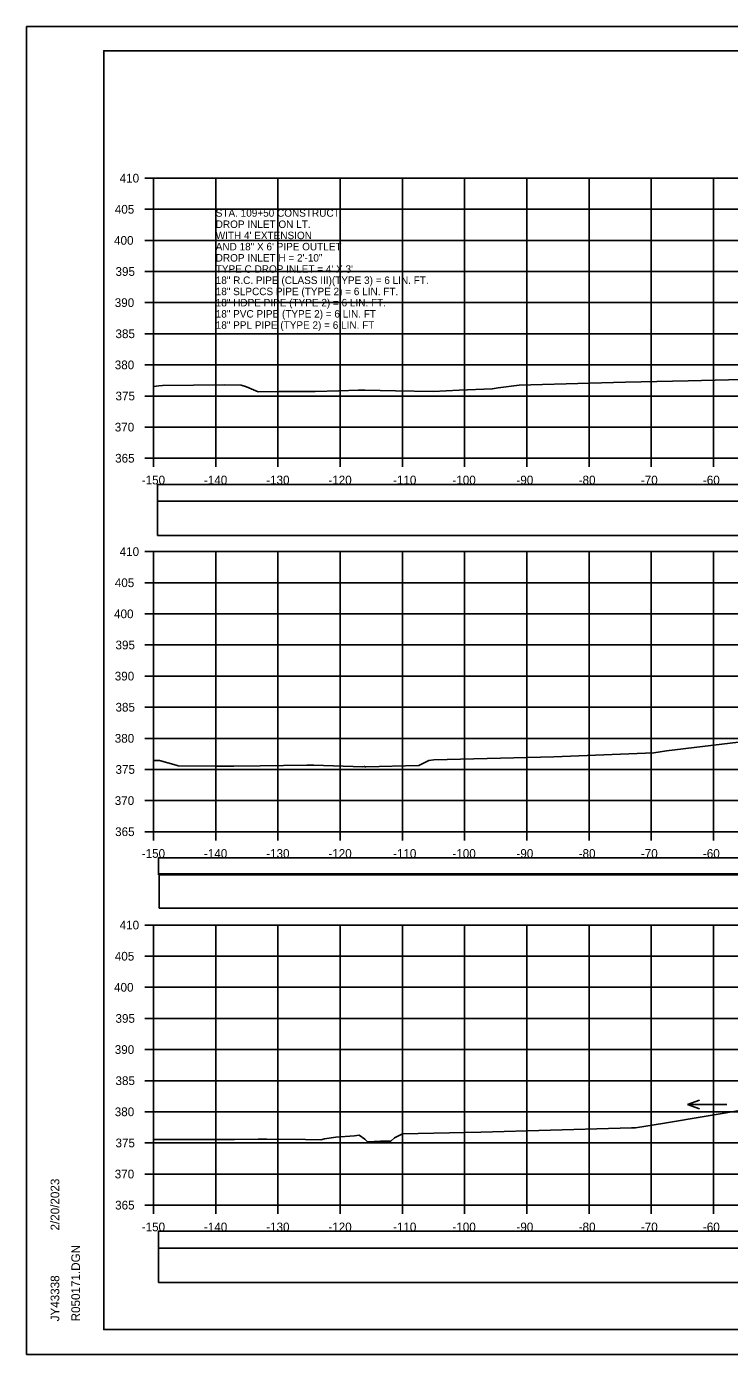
# Model space of a CAD drawing. Extents: x -37291014 to -37290680, y -936053 to -933067.
# Drawn here: x -37291013.5 to -37290900.5, y -934346.6 to -934133.3 of the extents above; entities that cross this region are included whole.
import ezdxf

# ---------------------------------------------------------------- set-up
doc = ezdxf.new("R2010")
doc.units = 0
for name, color, linetype in [('Default', 7, 'Continuous'), ('R_Axis', 7, 'Continuous'), ('R_Axis Annot', 7, 'Continuous'), ('R_Border', 7, 'Continuous'), ('R_Exist Surface', 7, 'Continuous'), ('R_Grid', 7, 'Continuous'), ('R_No Plot', 7, 'Continuous'), ('R_Water Annot', 7, 'Continuous')]:
    doc.layers.add(name, color=color, linetype=linetype)

msp = doc.modelspace()

# ---------------------------------------------------------------- linework, layer by layer
at = {"layer": 'Default'}
for points in [[(-37290992.48, -934209.53), (-37290693.72, -934209.53), (-37290693.72, -934206.82), (-37290992.48, -934206.82)], [(-37290992.48, -934215.05), (-37290693.72, -934215.05), (-37290693.72, -934209.53), (-37290992.48, -934209.53)], [(-37290992.31, -934269.53), (-37290693.89, -934269.53), (-37290693.89, -934266.82), (-37290992.31, -934266.82)], [(-37290992.18, -934274.93), (-37290693.77, -934274.93), (-37290693.77, -934269.4), (-37290992.18, -934269.4)], [(-37290992.31, -934329.53), (-37290693.89, -934329.53), (-37290693.89, -934326.82), (-37290992.31, -934326.82)], [(-37290992.31, -934335.05), (-37290693.89, -934335.05), (-37290693.89, -934329.53), (-37290992.31, -934329.53)]]:
    msp.add_lwpolyline(points, close=True, dxfattribs=at)
at = {"layer": 'R_Axis'}
for p, q in [((-37290994.5, -934157.62), (-37290993.1, -934157.62)), ((-37290993.1, -934202.62), (-37290993.1, -934157.62)), ((-37290994.5, -934162.62), (-37290993.1, -934162.62)), ((-37290994.5, -934167.62), (-37290993.1, -934167.62)), ((-37290994.5, -934172.62), (-37290993.1, -934172.62)), ((-37290994.5, -934177.62), (-37290993.1, -934177.62)), ((-37290994.5, -934182.62), (-37290993.1, -934182.62)), ((-37290994.5, -934187.62), (-37290993.1, -934187.62)), ((-37290994.5, -934192.62), (-37290993.1, -934192.62)), ((-37290994.5, -934197.62), (-37290993.1, -934197.62)), ((-37290994.5, -934202.62), (-37290993.1, -934202.62)), ((-37290993.1, -934202.62), (-37290693.1, -934202.62)), ((-37290993.1, -934204.02), (-37290993.1, -934202.62)), ((-37290983.1, -934204.02), (-37290983.1, -934202.62)), ((-37290973.1, -934204.02), (-37290973.1, -934202.62)), ((-37290963.1, -934204.02), (-37290963.1, -934202.62)), ((-37290953.1, -934204.02), (-37290953.1, -934202.62)), ((-37290943.1, -934204.02), (-37290943.1, -934202.62)), ((-37290933.1, -934204.02), (-37290933.1, -934202.62)), ((-37290923.1, -934204.02), (-37290923.1, -934202.62)), ((-37290913.1, -934204.02), (-37290913.1, -934202.62)), ((-37290903.1, -934204.02), (-37290903.1, -934202.62)), ((-37290994.5, -934217.62), (-37290993.1, -934217.62)), ((-37290993.1, -934262.62), (-37290993.1, -934217.62)), ((-37290994.5, -934222.62), (-37290993.1, -934222.62)), ((-37290994.5, -934227.62), (-37290993.1, -934227.62)), ((-37290994.5, -934232.62), (-37290993.1, -934232.62)), ((-37290994.5, -934237.62), (-37290993.1, -934237.62)), ((-37290994.5, -934242.62), (-37290993.1, -934242.62)), ((-37290994.5, -934247.62), (-37290993.1, -934247.62)), ((-37290994.5, -934252.62), (-37290993.1, -934252.62)), ((-37290994.5, -934257.62), (-37290993.1, -934257.62)), ((-37290994.5, -934262.62), (-37290993.1, -934262.62)), ((-37290993.1, -934262.62), (-37290693.1, -934262.62)), ((-37290993.1, -934264.02), (-37290993.1, -934262.62)), ((-37290983.1, -934264.02), (-37290983.1, -934262.62)), ((-37290973.1, -934264.02), (-37290973.1, -934262.62)), ((-37290963.1, -934264.02), (-37290963.1, -934262.62)), ((-37290953.1, -934264.02), (-37290953.1, -934262.62)), ((-37290943.1, -934264.02), (-37290943.1, -934262.62)), ((-37290933.1, -934264.02), (-37290933.1, -934262.62)), ((-37290923.1, -934264.02), (-37290923.1, -934262.62)), ((-37290913.1, -934264.02), (-37290913.1, -934262.62)), ((-37290903.1, -934264.02), (-37290903.1, -934262.62)), ((-37290994.5, -934277.62), (-37290993.1, -934277.62)), ((-37290993.1, -934322.62), (-37290993.1, -934277.62)), ((-37290994.5, -934282.62), (-37290993.1, -934282.62)), ((-37290994.5, -934287.62), (-37290993.1, -934287.62)), ((-37290994.5, -934292.62), (-37290993.1, -934292.62)), ((-37290994.5, -934297.62), (-37290993.1, -934297.62)), ((-37290994.5, -934302.62), (-37290993.1, -934302.62)), ((-37290994.5, -934307.62), (-37290993.1, -934307.62)), ((-37290994.5, -934312.62), (-37290993.1, -934312.62)), ((-37290994.5, -934317.62), (-37290993.1, -934317.62)), ((-37290994.5, -934322.62), (-37290993.1, -934322.62)), ((-37290993.1, -934322.62), (-37290693.1, -934322.62)), ((-37290993.1, -934324.02), (-37290993.1, -934322.62)), ((-37290983.1, -934324.02), (-37290983.1, -934322.62)), ((-37290973.1, -934324.02), (-37290973.1, -934322.62)), ((-37290963.1, -934324.02), (-37290963.1, -934322.62)), ((-37290953.1, -934324.02), (-37290953.1, -934322.62)), ((-37290943.1, -934324.02), (-37290943.1, -934322.62)), ((-37290933.1, -934324.02), (-37290933.1, -934322.62)), ((-37290923.1, -934324.02), (-37290923.1, -934322.62)), ((-37290913.1, -934324.02), (-37290913.1, -934322.62)), ((-37290903.1, -934324.02), (-37290903.1, -934322.62))]:
    msp.add_line(p, q, dxfattribs=at)
at = {"layer": 'R_Border'}
for p, q in [((-37291001.1, -934137.16), (-37290684.92, -934137.16)), ((-37291001.1, -934342.62), (-37291001.1, -934137.16)), ((-37291001.1, -934342.62), (-37291001.1, -934342.62)), ((-37290684.92, -934342.62), (-37291001.1, -934342.62))]:
    msp.add_line(p, q, dxfattribs=at)
at = {"layer": 'R_Exist Surface'}
for points in [[(-37290993.1, -934191.09), (-37290992.27, -934191), (-37290991.67, -934190.92), (-37290981.71, -934190.85), (-37290979.01, -934190.86), (-37290978.15, -934191.16), (-37290976.28, -934191.95), (-37290972.92, -934191.91), (-37290969.06, -934191.92), (-37290967.13, -934191.88), (-37290963.33, -934191.78), (-37290960.15, -934191.7), (-37290959.16, -934191.67), (-37290954.21, -934191.77), (-37290948.14, -934191.9), (-37290943.97, -934191.69), (-37290938.64, -934191.49), (-37290937.71, -934191.31), (-37290934.34, -934190.87), (-37290923, -934190.55), (-37290917.26, -934190.42), (-37290907.16, -934190.16), (-37290896.32, -934189.93)], [(-37290993.1, -934251.16), (-37290992.14, -934251.16), (-37290989.45, -934251.91), (-37290989.13, -934252.03), (-37290983.05, -934252.07), (-37290980.18, -934252.07), (-37290975.95, -934252.04), (-37290968.48, -934251.95), (-37290967.33, -934251.95), (-37290959.45, -934252.18), (-37290959.2, -934252.12), (-37290959.08, -934252.2), (-37290958.98, -934252.18), (-37290950.48, -934251.98), (-37290948.86, -934251.19), (-37290948.04, -934251.07), (-37290928.77, -934250.58), (-37290912.66, -934249.96), (-37290910.65, -934249.64), (-37290891.49, -934247.31)], [(-37290993.1, -934312.05), (-37290991.48, -934312.06), (-37290986.25, -934312.09), (-37290980.1, -934312.06), (-37290976.26, -934312.03), (-37290974.89, -934312.02), (-37290968.69, -934312.06), (-37290966.2, -934312.13), (-37290965.62, -934311.97), (-37290963.78, -934311.68), (-37290960.82, -934311.49), (-37290960.02, -934311.38), (-37290959.11, -934312.02), (-37290958.71, -934312.46), (-37290956.62, -934312.33), (-37290954.93, -934312.33), (-37290954.35, -934311.78), (-37290953.07, -934311.18), (-37290940.48, -934310.9), (-37290918.09, -934310.25), (-37290916.26, -934310.2), (-37290915.63, -934310.18), (-37290910.94, -934309.42), (-37290877.81, -934303.86)]]:
    msp.add_lwpolyline(points, dxfattribs=at)
at = {"layer": 'R_Grid'}
for p, q in [((-37290993.1, -934157.62), (-37290693.1, -934157.62)), ((-37290993.1, -934202.62), (-37290993.1, -934157.62)), ((-37290983.1, -934202.62), (-37290983.1, -934157.62)), ((-37290973.1, -934202.62), (-37290973.1, -934157.62)), ((-37290963.1, -934202.62), (-37290963.1, -934157.62)), ((-37290953.1, -934202.62), (-37290953.1, -934157.62)), ((-37290943.1, -934202.62), (-37290943.1, -934157.62)), ((-37290933.1, -934202.62), (-37290933.1, -934157.62)), ((-37290923.1, -934202.62), (-37290923.1, -934157.62)), ((-37290913.1, -934202.62), (-37290913.1, -934157.62)), ((-37290903.1, -934202.62), (-37290903.1, -934157.62)), ((-37290993.1, -934162.62), (-37290693.1, -934162.62)), ((-37290993.1, -934167.62), (-37290693.1, -934167.62)), ((-37290993.1, -934172.62), (-37290693.1, -934172.62)), ((-37290993.1, -934177.62), (-37290693.1, -934177.62)), ((-37290993.1, -934182.62), (-37290693.1, -934182.62)), ((-37290993.1, -934187.62), (-37290693.1, -934187.62)), ((-37290993.1, -934192.62), (-37290693.1, -934192.62)), ((-37290993.1, -934197.62), (-37290693.1, -934197.62)), ((-37290993.1, -934202.62), (-37290693.1, -934202.62)), ((-37290993.1, -934217.62), (-37290693.1, -934217.62)), ((-37290993.1, -934262.62), (-37290993.1, -934217.62)), ((-37290983.1, -934262.62), (-37290983.1, -934217.62)), ((-37290973.1, -934262.62), (-37290973.1, -934217.62)), ((-37290963.1, -934262.62), (-37290963.1, -934217.62)), ((-37290953.1, -934262.62), (-37290953.1, -934217.62)), ((-37290943.1, -934262.62), (-37290943.1, -934217.62)), ((-37290933.1, -934262.62), (-37290933.1, -934217.62)), ((-37290923.1, -934262.62), (-37290923.1, -934217.62)), ((-37290913.1, -934262.62), (-37290913.1, -934217.62)), ((-37290903.1, -934262.62), (-37290903.1, -934217.62)), ((-37290993.1, -934222.62), (-37290693.1, -934222.62)), ((-37290993.1, -934227.62), (-37290693.1, -934227.62)), ((-37290993.1, -934232.62), (-37290693.1, -934232.62)), ((-37290993.1, -934237.62), (-37290693.1, -934237.62)), ((-37290993.1, -934242.62), (-37290693.1, -934242.62)), ((-37290993.1, -934247.62), (-37290693.1, -934247.62)), ((-37290993.1, -934252.62), (-37290693.1, -934252.62)), ((-37290993.1, -934257.62), (-37290693.1, -934257.62)), ((-37290993.1, -934262.62), (-37290693.1, -934262.62)), ((-37290993.1, -934277.62), (-37290693.1, -934277.62)), ((-37290993.1, -934322.62), (-37290993.1, -934277.62)), ((-37290983.1, -934322.62), (-37290983.1, -934277.62)), ((-37290973.1, -934322.62), (-37290973.1, -934277.62)), ((-37290963.1, -934322.62), (-37290963.1, -934277.62)), ((-37290953.1, -934322.62), (-37290953.1, -934277.62)), ((-37290943.1, -934322.62), (-37290943.1, -934277.62)), ((-37290933.1, -934322.62), (-37290933.1, -934277.62)), ((-37290923.1, -934322.62), (-37290923.1, -934277.62)), ((-37290913.1, -934322.62), (-37290913.1, -934277.62)), ((-37290903.1, -934322.62), (-37290903.1, -934277.62)), ((-37290993.1, -934282.62), (-37290693.1, -934282.62)), ((-37290993.1, -934287.62), (-37290693.1, -934287.62)), ((-37290993.1, -934292.62), (-37290693.1, -934292.62)), ((-37290993.1, -934297.62), (-37290693.1, -934297.62)), ((-37290993.1, -934302.62), (-37290693.1, -934302.62)), ((-37290993.1, -934307.62), (-37290693.1, -934307.62)), ((-37290993.1, -934312.62), (-37290693.1, -934312.62)), ((-37290993.1, -934317.62), (-37290693.1, -934317.62)), ((-37290993.1, -934322.62), (-37290693.1, -934322.62))]:
    msp.add_line(p, q, dxfattribs=at)
at = {"layer": 'R_No Plot'}
for p, q in [((-37291013.5, -934133.27), (-37290680.17, -934133.27)), ((-37291013.5, -934346.6), (-37290680.17, -934346.6))]:
    msp.add_line(p, q, dxfattribs=at)
for points in [[(-37291013.51, -934133.27), (-37290680.17, -934133.27), (-37290680.17, -934346.6), (-37291013.51, -934346.6)], [(-37290767.18, -934137.16), (-37290747.56, -934137.16), (-37290747.56, -934147.04), (-37290731.45, -934147.04), (-37290708.25, -934147.04), (-37290708.25, -934171.37), (-37290684.92, -934171.37), (-37290684.92, -934342.62), (-37291001.1, -934342.62), (-37291001.1, -934137.16)]]:
    msp.add_lwpolyline(points, close=True, dxfattribs=at)
at = {"layer": 'R_Water Annot'}
for p, q in [((-37290907.26, -934306.47), (-37290905.33, -934305.77)), ((-37290900.97, -934306.47), (-37290907.26, -934306.47)), ((-37290907.26, -934306.47), (-37290905.33, -934307.17))]:
    msp.add_line(p, q, dxfattribs=at)

# ---------------------------------------------------------------- texts
at = {"layer": 'R_Axis Annot'}
for s, p in [('410', (-37290998.54, -934158.32)), ('405', (-37290999.32, -934163.32)), ('400', (-37290999.44, -934168.32)), ('395', (-37290999.21, -934173.32)), ('390', (-37290999.33, -934178.32)), ('385', (-37290999.21, -934183.32)), ('380', (-37290999.33, -934188.32)), ('375', (-37290999.21, -934193.32)), ('370', (-37290999.33, -934198.32)), ('365', (-37290999.27, -934203.32)), ('-150', (-37290994.99, -934206.82)), ('-140', (-37290984.99, -934206.82)), ('-130', (-37290974.99, -934206.82)), ('-120', (-37290964.99, -934206.82)), ('-110', (-37290954.6, -934206.82)), ('-100', (-37290945.05, -934206.82)), ('-90', (-37290934.76, -934206.82)), ('-80', (-37290924.76, -934206.82)), ('-70', (-37290914.76, -934206.82)), ('-60', (-37290904.79, -934206.82)), ('410', (-37290998.54, -934218.32)), ('405', (-37290999.32, -934223.32)), ('400', (-37290999.44, -934228.32)), ('395', (-37290999.21, -934233.32)), ('390', (-37290999.33, -934238.32)), ('385', (-37290999.21, -934243.32)), ('380', (-37290999.33, -934248.32)), ('375', (-37290999.21, -934253.32)), ('370', (-37290999.33, -934258.32)), ('365', (-37290999.27, -934263.32)), ('-150', (-37290994.99, -934266.82)), ('-140', (-37290984.99, -934266.82)), ('-130', (-37290974.99, -934266.82)), ('-120', (-37290964.99, -934266.82)), ('-110', (-37290954.6, -934266.82)), ('-100', (-37290945.05, -934266.82)), ('-90', (-37290934.76, -934266.82)), ('-80', (-37290924.76, -934266.82)), ('-70', (-37290914.76, -934266.82)), ('-60', (-37290904.79, -934266.82)), ('410', (-37290998.54, -934278.32)), ('405', (-37290999.32, -934283.32)), ('400', (-37290999.44, -934288.32)), ('395', (-37290999.21, -934293.32)), ('390', (-37290999.33, -934298.32)), ('385', (-37290999.21, -934303.32)), ('380', (-37290999.33, -934308.32)), ('375', (-37290999.21, -934313.32)), ('370', (-37290999.33, -934318.32)), ('365', (-37290999.27, -934323.32)), ('-150', (-37290994.99, -934326.82)), ('-140', (-37290984.99, -934326.82)), ('-130', (-37290974.99, -934326.82)), ('-120', (-37290964.99, -934326.82)), ('-110', (-37290954.6, -934326.82)), ('-100', (-37290945.05, -934326.82)), ('-90', (-37290934.76, -934326.82)), ('-80', (-37290924.76, -934326.82)), ('-70', (-37290914.76, -934326.82)), ('-60', (-37290904.79, -934326.82))]:
    msp.add_text(s, height=1.4, dxfattribs=at).set_placement(p)
at = {"layer": 'R_Border'}
for s, p in [('2/20/2023', (-37291008.24, -934326.69)), ('R050171.DGN', (-37291004.91, -934341.29)), ('JY43338', (-37291008.24, -934341.29))]:
    msp.add_text(s, height=1.4, rotation=90, dxfattribs=at).set_placement(p)
at = {"layer": 'R_Water Annot'}
for s, p in [('STA. 109+50 CONSTRUCT', (-37290983.1, -934163.82)), ('DROP INLET ON LT.', (-37290983.1, -934165.62)), ("WITH 4' EXTENSION", (-37290983.1, -934167.42)), ('AND 18" X 6\' PIPE OUTLET', (-37290983.1, -934169.22)), ("TYPE C DROP INLET = 4' X 3'", (-37290983.1, -934172.82)), ('DROP INLET H = 2\'-10"', (-37290983.1, -934171.02)), ('18" R.C. PIPE (CLASS III)(TYPE 3) = 6 LIN. FT.', (-37290983.1, -934174.62)), ('18" SLPCCS PIPE (TYPE 2) = 6 LIN. FT.', (-37290983.1, -934176.42)), ('18" HDPE PIPE (TYPE 2) = 6 LIN. FT.', (-37290983.1, -934178.22)), ('18" PVC PIPE (TYPE 2) = 6 LIN. FT', (-37290983.1, -934180.02)), ('18" PPL PIPE (TYPE 2) = 6 LIN. FT', (-37290983.1, -934181.82))]:
    msp.add_text(s, height=1.2, dxfattribs=at).set_placement(p)

doc.saveas('drawing.dxf')
